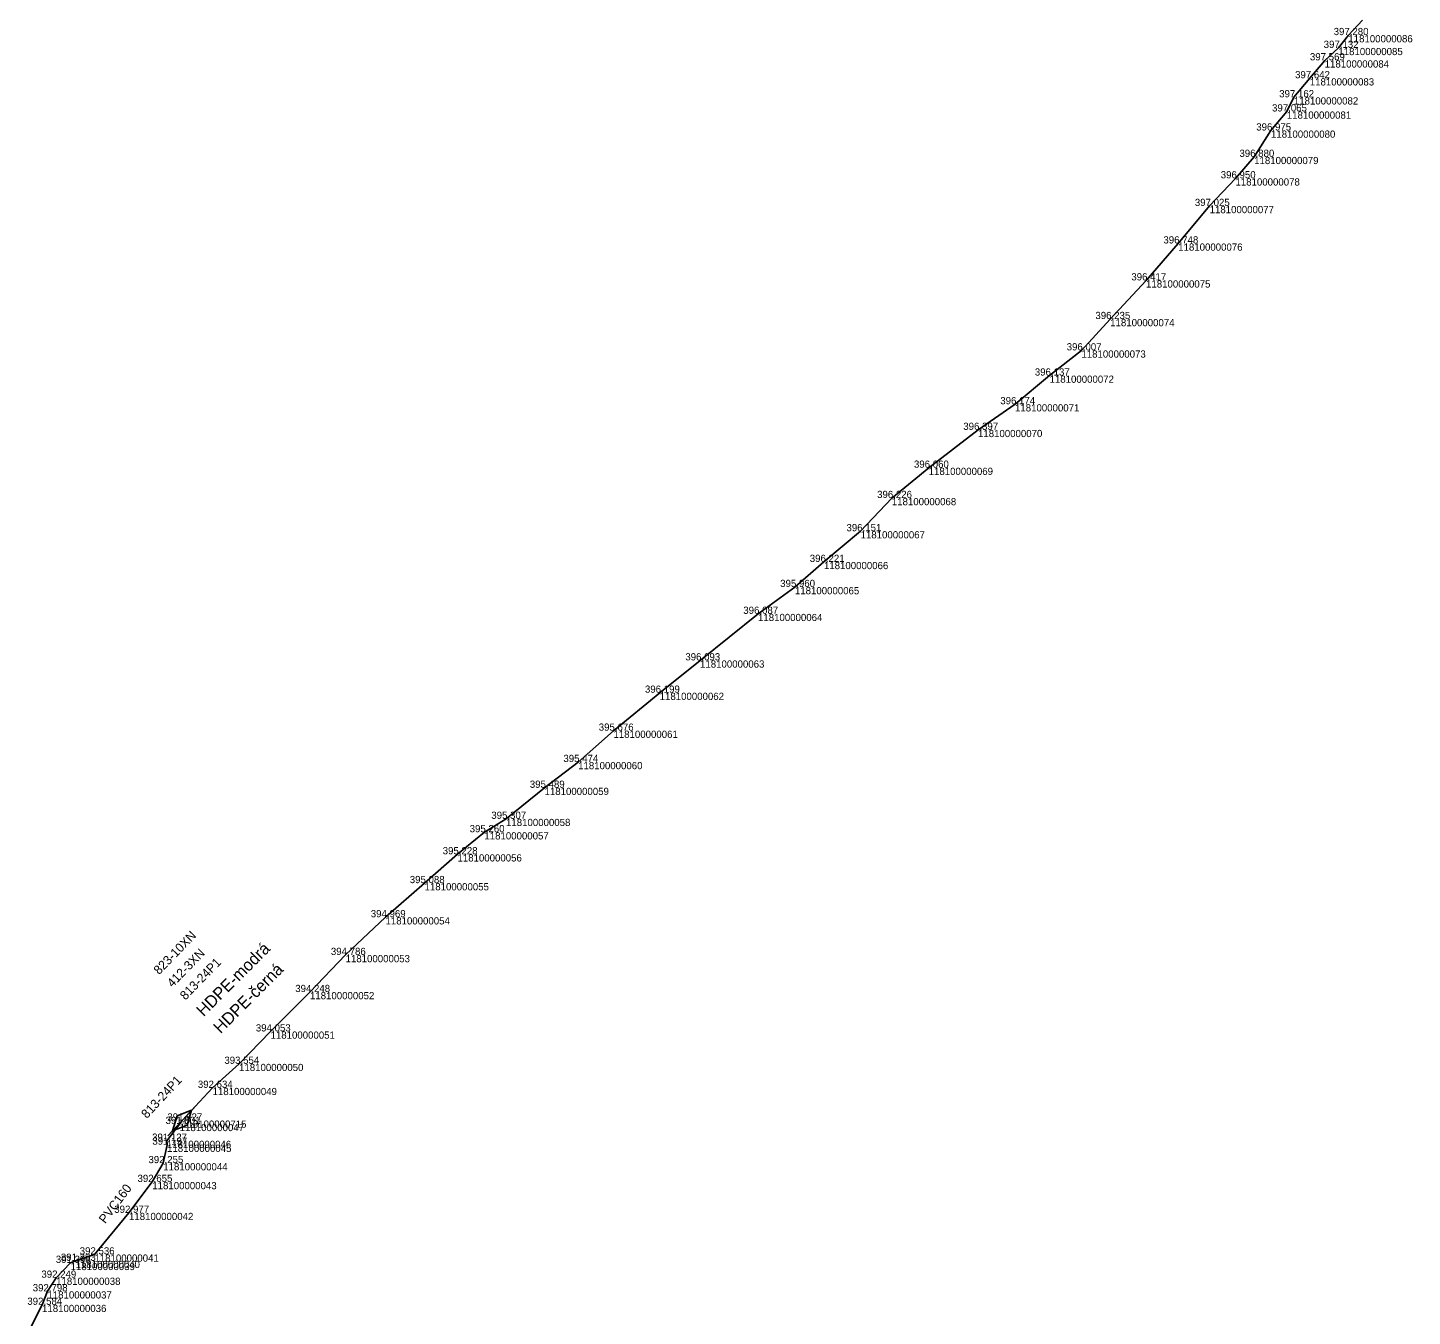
# Model space of a CAD drawing. Extents: x -724084 to -720954, y -948423 to -945131.
# Drawn here: x -721877.2 to -721646.7, y -947200 to -946985.5 of the extents above; entities that cross this region are included whole.
import ezdxf

# ---------------------------------------------------------------- set-up
doc = ezdxf.new("R2010")
doc.units = 0
for name, color, linetype in [('Vrstva 28', 7, 'Continuous'), ('Vrstva 31', 7, 'Continuous'), ('Vrstva 33', 7, 'Continuous'), ('Vrstva 35', 7, 'Continuous'), ('Vrstva 60', 7, 'Continuous'), ('Vrstva 61', 7, 'Continuous')]:
    doc.layers.add(name, color=color, linetype=linetype)

msp = doc.modelspace()

# ---------------------------------------------------------------- linework, layer by layer
at = {"layer": 'Vrstva 28'}
for p, q in [((-721853.85, -947169.94), (-721849.09, -947164.83)), ((-721852.32, -947166.59), (-721849.88, -947165.68)), ((-721849.88, -947165.68), (-721850.62, -947168.18)), ((-721853.06, -947169.09), (-721852.32, -947166.59)), ((-721850.62, -947168.18), (-721853.06, -947169.09))]:
    msp.add_line(p, q, dxfattribs=at)
msp.add_lwpolyline([(-721876.72, -947201.88), (-721874.78, -947198.06), (-721873.88, -947195.81), (-721872.44, -947193.55), (-721870.03, -947191.08), (-721869.2, -947190.74), (-721866.06, -947189.68), (-721860.31, -947182.75), (-721856.43, -947177.61), (-721854.61, -947174.48), (-721853.97, -947171.41), (-721854.01, -947170.75), (-721851.87, -947167.95), (-721851.47, -947167.39), (-721846.4, -947161.95), (-721841.99, -947157.95), (-721836.75, -947152.56), (-721830.19, -947146), (-721824.26, -947139.83), (-721817.62, -947133.55), (-721811.12, -947127.87), (-721805.64, -947123.07), (-721801.16, -947119.4), (-721797.56, -947117.17), (-721791.15, -947112), (-721785.56, -947107.71), (-721779.68, -947102.5), (-721771.99, -947096.18), (-721765.27, -947090.8), (-721755.62, -947083.05), (-721749.48, -947078.58), (-721744.65, -947074.41), (-721738.55, -947069.3), (-721733.35, -947063.77), (-721727.22, -947058.73), (-721719.01, -947052.43), (-721712.85, -947048.16), (-721707.1, -947043.39), (-721701.8, -947039.2), (-721697.01, -947033.98), (-721691.04, -947027.55), (-721685.69, -947021.4), (-721680.46, -947015.16), (-721676.16, -947010.56), (-721673.05, -947006.99), (-721670.25, -947002.6), (-721667.61, -946999.43), (-721666.44, -946997.07), (-721663.79, -946993.9), (-721661.31, -946990.92), (-721659.03, -946988.85), (-721657.37, -946986.72), (-721655.02, -946984.24)], dxfattribs=at)
at = {"layer": 'Vrstva 31'}
msp.add_lwpolyline([(-721876.72, -947201.88), (-721874.78, -947198.06), (-721873.88, -947195.81), (-721872.44, -947193.55), (-721870.03, -947191.08), (-721869.2, -947190.74), (-721866.06, -947189.68), (-721860.31, -947182.75), (-721856.43, -947177.61), (-721854.61, -947174.48), (-721853.97, -947171.41), (-721854.01, -947170.75), (-721851.87, -947167.95), (-721851.47, -947167.39), (-721846.4, -947161.95), (-721841.99, -947157.95), (-721836.75, -947152.56), (-721830.19, -947146), (-721824.26, -947139.83), (-721817.62, -947133.55), (-721811.12, -947127.87), (-721805.64, -947123.07), (-721801.16, -947119.4), (-721797.56, -947117.17), (-721791.15, -947112), (-721785.56, -947107.71), (-721779.68, -947102.5), (-721771.99, -947096.18), (-721765.27, -947090.8), (-721755.62, -947083.05), (-721749.48, -947078.58), (-721744.65, -947074.41), (-721738.55, -947069.3), (-721733.35, -947063.77), (-721727.22, -947058.73), (-721719.01, -947052.43), (-721712.85, -947048.16), (-721707.1, -947043.39), (-721701.8, -947039.2), (-721697.01, -947033.98), (-721691.04, -947027.55), (-721685.69, -947021.4), (-721680.46, -947015.16), (-721676.16, -947010.56), (-721673.05, -947006.99), (-721670.25, -947002.6), (-721667.61, -946999.43), (-721666.44, -946997.07), (-721663.79, -946993.9), (-721661.31, -946990.92), (-721659.03, -946988.85), (-721657.37, -946986.72), (-721655.02, -946984.24)], dxfattribs=at)
at = {"layer": 'Vrstva 33'}
msp.add_lwpolyline([(-721876.72, -947201.88), (-721874.78, -947198.06), (-721873.88, -947195.81), (-721872.44, -947193.55), (-721870.03, -947191.08), (-721869.2, -947190.74), (-721866.06, -947189.68), (-721860.31, -947182.75), (-721856.43, -947177.61), (-721854.61, -947174.48), (-721853.97, -947171.41), (-721854.01, -947170.75), (-721851.87, -947167.95), (-721851.47, -947167.39), (-721846.4, -947161.95), (-721841.99, -947157.95), (-721836.75, -947152.56), (-721830.19, -947146), (-721824.26, -947139.83), (-721817.62, -947133.55), (-721811.12, -947127.87), (-721805.64, -947123.07), (-721801.16, -947119.4), (-721797.56, -947117.17), (-721791.15, -947112), (-721785.56, -947107.71), (-721779.68, -947102.5), (-721771.99, -947096.18), (-721765.27, -947090.8), (-721755.62, -947083.05), (-721749.48, -947078.58), (-721744.65, -947074.41), (-721738.55, -947069.3), (-721733.35, -947063.77), (-721727.22, -947058.73), (-721719.01, -947052.43), (-721712.85, -947048.16), (-721707.1, -947043.39), (-721701.8, -947039.2), (-721697.01, -947033.98), (-721691.04, -947027.55), (-721685.69, -947021.4), (-721680.46, -947015.16), (-721676.16, -947010.56), (-721673.05, -947006.99), (-721670.25, -947002.6), (-721667.61, -946999.43), (-721666.44, -946997.07), (-721663.79, -946993.9), (-721661.31, -946990.92), (-721659.03, -946988.85), (-721657.37, -946986.72), (-721655.02, -946984.24)], dxfattribs=at)
at = {"layer": 'Vrstva 35'}
msp.add_lwpolyline([(-721872.44, -947193.55), (-721870.03, -947191.08), (-721869.2, -947190.74), (-721866.06, -947189.68), (-721860.31, -947182.75), (-721856.43, -947177.61), (-721854.61, -947174.48), (-721853.97, -947171.41), (-721854.01, -947170.75), (-721851.87, -947167.95)], dxfattribs=at)
at = {"layer": 'Vrstva 60'}
for p, q in [((-721657.37, -946986.72), (-721657.37, -946986.72)), ((-721659.03, -946988.85), (-721659.03, -946988.85)), ((-721661.31, -946990.92), (-721661.31, -946990.92)), ((-721663.79, -946993.9), (-721663.79, -946993.9)), ((-721666.44, -946997.07), (-721666.44, -946997.07)), ((-721667.61, -946999.43), (-721667.61, -946999.43)), ((-721670.25, -947002.6), (-721670.25, -947002.6)), ((-721673.05, -947006.99), (-721673.05, -947006.99)), ((-721676.16, -947010.56), (-721676.16, -947010.56)), ((-721680.46, -947015.16), (-721680.46, -947015.16)), ((-721685.69, -947021.4), (-721685.69, -947021.4)), ((-721691.04, -947027.55), (-721691.04, -947027.55)), ((-721697.01, -947033.98), (-721697.01, -947033.98)), ((-721701.8, -947039.2), (-721701.8, -947039.2)), ((-721707.1, -947043.39), (-721707.1, -947043.39)), ((-721712.85, -947048.16), (-721712.85, -947048.16)), ((-721719.01, -947052.43), (-721719.01, -947052.43)), ((-721727.22, -947058.73), (-721727.22, -947058.73)), ((-721733.35, -947063.77), (-721733.35, -947063.77)), ((-721738.55, -947069.3), (-721738.55, -947069.3)), ((-721744.65, -947074.41), (-721744.65, -947074.41)), ((-721749.48, -947078.58), (-721749.48, -947078.58)), ((-721755.62, -947083.05), (-721755.62, -947083.05)), ((-721765.27, -947090.8), (-721765.27, -947090.8)), ((-721771.99, -947096.18), (-721771.99, -947096.18)), ((-721779.68, -947102.5), (-721779.68, -947102.5)), ((-721785.56, -947107.71), (-721785.56, -947107.71)), ((-721791.15, -947112), (-721791.15, -947112)), ((-721797.56, -947117.17), (-721797.56, -947117.17)), ((-721801.16, -947119.4), (-721801.16, -947119.4)), ((-721805.64, -947123.07), (-721805.64, -947123.07)), ((-721811.12, -947127.87), (-721811.12, -947127.87)), ((-721817.62, -947133.55), (-721817.62, -947133.55)), ((-721824.26, -947139.83), (-721824.26, -947139.83)), ((-721830.19, -947146), (-721830.19, -947146)), ((-721836.75, -947152.56), (-721836.75, -947152.56)), ((-721841.99, -947157.95), (-721841.99, -947157.95)), ((-721846.4, -947161.95), (-721846.4, -947161.95)), ((-721851.87, -947167.95), (-721851.87, -947167.95)), ((-721851.47, -947167.39), (-721851.47, -947167.39)), ((-721854.01, -947170.75), (-721854.01, -947170.75)), ((-721853.97, -947171.41), (-721853.97, -947171.41)), ((-721854.61, -947174.48), (-721854.61, -947174.48)), ((-721856.43, -947177.61), (-721856.43, -947177.61)), ((-721860.31, -947182.75), (-721860.31, -947182.75)), ((-721870.03, -947191.08), (-721870.03, -947191.08)), ((-721869.2, -947190.74), (-721869.2, -947190.74)), ((-721866.06, -947189.68), (-721866.06, -947189.68)), ((-721872.44, -947193.55), (-721872.44, -947193.55)), ((-721873.88, -947195.81), (-721873.88, -947195.81)), ((-721874.78, -947198.06), (-721874.78, -947198.06))]:
    msp.add_line(p, q, dxfattribs=at)

# ---------------------------------------------------------------- texts
at = {"layer": 'Vrstva 28'}
for s, rotation, p in [('412-3XN', 45.7766, (-721853.07, -947145.33)), ('813-24P1', 45.7766, (-721850.92, -947147.43)), ('813-24P1', 47.0024, (-721857.34, -947167.15))]:
    msp.add_text(s, height=1.5, rotation=rotation, dxfattribs=at).set_placement(p)
at = {"layer": 'Vrstva 31'}
msp.add_text('823-10XN', height=1.5, rotation=45.7766, dxfattribs=at).set_placement((-721855.3, -947143.2))
at = {"layer": 'Vrstva 33'}
for s, p in [('HDPE-modrá', (-721847.9, -947150.2)), ('HDPE-černá', (-721845.07, -947153.03))]:
    msp.add_text(s, height=2, rotation=45, dxfattribs=at).set_placement(p)
at = {"layer": 'Vrstva 35'}
msp.add_text('PVC160', height=1.5, rotation=52.9253, dxfattribs=at).set_placement((-721864.27, -947184.64))
at = {"layer": 'Vrstva 60'}
for s, p in [('118100000086', (-721657.37, -946987.92)), ('118100000085', (-721659.03, -946990.05)), ('118100000084', (-721661.31, -946992.12)), ('118100000083', (-721663.79, -946995.1)), ('118100000082', (-721666.44, -946998.27)), ('118100000081', (-721667.61, -947000.63)), ('118100000080', (-721670.25, -947003.8)), ('118100000079', (-721673.05, -947008.19)), ('118100000078', (-721676.16, -947011.76)), ('118100000077', (-721680.46, -947016.36)), ('118100000076', (-721685.69, -947022.6)), ('118100000075', (-721691.04, -947028.74)), ('118100000074', (-721697.01, -947035.18)), ('118100000073', (-721701.8, -947040.4)), ('118100000072', (-721707.1, -947044.59)), ('118100000071', (-721712.85, -947049.36)), ('118100000070', (-721719.01, -947053.63)), ('118100000069', (-721727.22, -947059.93)), ('118100000068', (-721733.35, -947064.97)), ('118100000067', (-721738.55, -947070.49)), ('118100000066', (-721744.65, -947075.61)), ('118100000065', (-721749.48, -947079.79)), ('118100000064', (-721755.62, -947084.25)), ('118100000063', (-721765.27, -947092)), ('118100000062', (-721771.99, -947097.38)), ('118100000061', (-721779.68, -947103.7)), ('118100000060', (-721785.56, -947108.91)), ('118100000059', (-721791.15, -947113.2)), ('118100000058', (-721797.56, -947118.37)), ('118100000057', (-721801.16, -947120.6)), ('118100000056', (-721805.64, -947124.27)), ('118100000055', (-721811.12, -947129.07)), ('118100000054', (-721817.62, -947134.75)), ('118100000053', (-721824.26, -947141.04)), ('118100000052', (-721830.19, -947147.2)), ('118100000051', (-721836.75, -947153.76)), ('118100000050', (-721841.99, -947159.15)), ('118100000049', (-721846.4, -947163.15)), ('118100000047', (-721851.87, -947169.15)), ('118100000715', (-721851.47, -947168.58)), ('118100000046', (-721854.01, -947171.95)), ('118100000045', (-721853.97, -947172.61)), ('118100000044', (-721854.61, -947175.68)), ('118100000043', (-721856.43, -947178.82)), ('118100000042', (-721860.31, -947183.95)), ('118100000039', (-721870.03, -947192.28)), ('118100000040', (-721869.2, -947191.94)), ('118100000041', (-721866.06, -947190.88)), ('118100000038', (-721872.44, -947194.74)), ('118100000037', (-721873.88, -947197.01)), ('118100000036', (-721874.78, -947199.26))]:
    msp.add_text(s, height=1.2, dxfattribs=at).set_placement(p)
at = {"layer": 'Vrstva 61'}
for s, p in [('397.280', (-721659.82, -946986.72)), ('397.132', (-721661.48, -946988.85)), ('397.569', (-721663.77, -946990.92)), ('397.642', (-721666.24, -946993.9)), ('397.162', (-721668.88, -946997.07)), ('397.065', (-721670.07, -946999.43)), ('396.975', (-721672.7, -947002.6)), ('396.880', (-721675.5, -947006.99)), ('396.950', (-721678.61, -947010.56)), ('397.025', (-721682.92, -947015.16)), ('396.748', (-721688.15, -947021.4)), ('396.417', (-721693.49, -947027.55)), ('396.235', (-721699.47, -947033.98)), ('396.007', (-721704.25, -947039.2)), ('396.137', (-721709.55, -947043.39)), ('396.174', (-721715.3, -947048.16)), ('396.397', (-721721.46, -947052.43)), ('396.060', (-721729.67, -947058.73)), ('396.226', (-721735.8, -947063.77)), ('396.151', (-721740.9, -947069.3)), ('396.221', (-721747.01, -947074.41)), ('395.960', (-721751.93, -947078.58)), ('396.087', (-721758.07, -947083.05)), ('396.093', (-721767.72, -947090.8)), ('396.199', (-721774.44, -947096.18)), ('395.676', (-721782.13, -947102.5)), ('395.474', (-721788.01, -947107.71)), ('395.489', (-721793.6, -947112)), ('395.307', (-721800.01, -947117.17)), ('395.260', (-721803.61, -947119.4)), ('395.228', (-721808.1, -947123.07)), ('395.088', (-721813.58, -947127.87)), ('394.969', (-721820.07, -947133.55)), ('394.786', (-721826.71, -947139.83)), ('394.248', (-721832.64, -947146)), ('394.053', (-721839.2, -947152.56)), ('393.554', (-721844.44, -947157.95)), ('392.634', (-721848.85, -947161.95)), ('391.827', (-721853.92, -947167.39)), ('391.801', (-721854.22, -947167.95)), ('391.127', (-721856.46, -947170.75)), ('391.197', (-721856.42, -947171.41)), ('392.255', (-721857.07, -947174.48)), ('392.655', (-721858.89, -947177.61)), ('392.977', (-721862.76, -947182.75)), ('391.383', (-721871.65, -947190.74)), ('392.536', (-721868.51, -947189.68)), ('391.398', (-721872.49, -947191.08)), ('392.249', (-721874.89, -947193.55)), ('392.798', (-721876.33, -947195.81)), ('392.584', (-721877.23, -947198.06))]:
    msp.add_text(s, height=1.2, dxfattribs=at).set_placement(p)

doc.saveas('drawing.dxf')
